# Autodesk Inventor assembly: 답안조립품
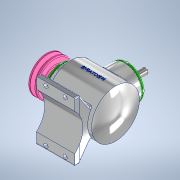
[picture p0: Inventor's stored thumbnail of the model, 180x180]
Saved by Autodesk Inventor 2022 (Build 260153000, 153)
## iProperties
Created: 2023-04
Part Number: 답안조립품
Document SubType Name: Assembly
Designer: Admin
Author: Admin
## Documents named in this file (17)
- C:\Users\Admin\Desktop\730411V1004\답안조립품.iam
- C:\Users\Admin\Desktop\730411V1004\본체.ipt
- C:\Users\Admin\Desktop\730411V1004\커버.ipt
- C:\Users\Admin\Desktop\730411V1004\베어링 6203.ipt
- C:\Users\Admin\Desktop\730411V1004\오일실 17 x 32 x 8.ipt
- C:\Users\Admin\Desktop\730411V1004\메인 축.ipt
- 메인 축.ipt
- C:\Users\Admin\Desktop\730411V1004\키 5 x 5 x 14.ipt
- C:\Users\Admin\Desktop\730411V1004\메인 베벨기어.ipt
- C:\Users\Admin\Desktop\730411V1004\서브 축.ipt
- 서브 축.ipt
- C:\Users\Admin\Desktop\730411V1004\키 4 x 4 x 14.ipt
- C:\Users\Admin\Desktop\730411V1004\서브 베벨기어.ipt
- C:\Users\Admin\Desktop\730411V1004\V-벨트풀리.ipt
- C:\Users\Admin\Desktop\730411V1004\볼트 M4 x 10.ipt
- C:\Users\Admin\Desktop\730411V1004\와셔 4 x 16.ipt
- C:\Users\Admin\Desktop\730411V1004\육각볼트 M4 x 8.ipt
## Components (1 placed, 1 different names)
1. V-벨트풀리:1
